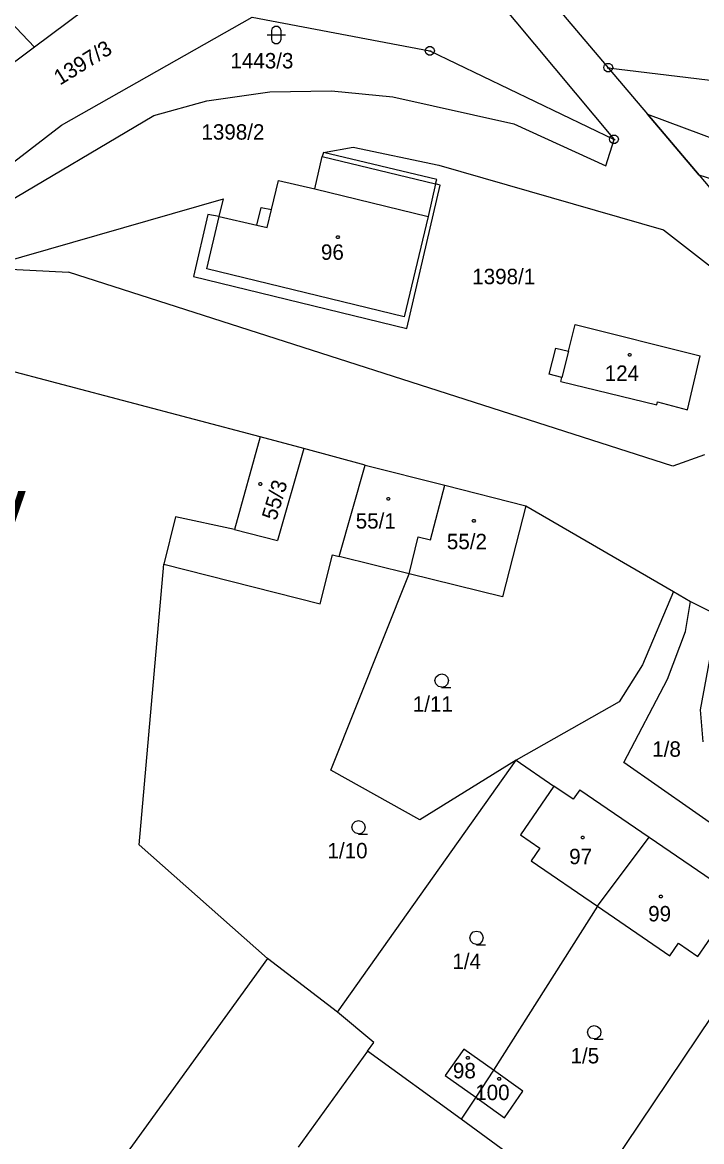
# Model space of a CAD drawing. Extents: x -850689 to -847910, y -1058374 to -1054747.
# Drawn here: x -849326.1 to -849251.2, y -1056373.6 to -1056250.1 of the extents above; entities that cross this region are included whole.
import ezdxf

# ---------------------------------------------------------------- set-up
doc = ezdxf.new("R2010")
doc.units = 0
for name, color, linetype in [('KN_BREMENA', 7, 'Continuous'), ('KN_HRANICE', 7, 'Continuous'), ('KN_KULTURY', 7, 'Continuous'), ('KN_MEZNIKY', 7, 'Continuous'), ('KN_PARCELY', 7, 'Continuous'), ('KN_SLUCKY', 7, 'Continuous'), ('KN_STAVEBNI', 7, 'Continuous')]:
    doc.layers.add(name, color=color, linetype=linetype)

# ---------------------------------------------------------------- blocks, each defined once
blk = doc.blocks.new('304')
blk.add_lwpolyline([(0, 0), (-0.38, 0.1), (-0.65, 0.37), (-0.75, 0.74), (-0.65, 1.11), (-0.38, 1.38), (-0.01, 1.48), (0.36, 1.38), (0.63, 1.11), (0.73, 0.73), (0.63, 0.35), (0.36, 0.08), (-0.02, -0.02), (0.98, -0.02)])
blk = doc.blocks.new('316')
for points in [[(-0.5, 1.5), (-0.4, 1.79), (-0.15, 1.97), (0.16, 1.97), (0.41, 1.79), (0.51, 1.5), (0.51, 0.5), (0.41, 0.21), (0.16, 0.03), (-0.15, 0.03), (-0.4, 0.21), (-0.5, 0.5), (-0.5, 1.5)], [(-1, 1), (0.27, 1), (1, 1)]]:
    blk.add_lwpolyline(points)
blk = doc.blocks.new('105')
blk.add_line((-0.12, 0), (0.12, 0))
blk.add_lwpolyline([(0.15, 0.48), (0.4, 0.3), (0.5, 0.01), (0.4, -0.28), (0.15, -0.46), (-0.16, -0.46), (-0.41, -0.28), (-0.51, 0.01), (-0.41, 0.3), (-0.16, 0.48), (0.15, 0.48)])
blk = doc.blocks.new('402')
blk.add_lwpolyline([(0.09, 0.15), (0.18, 0), (0.09, -0.15), (-0.09, -0.15), (-0.18, 0), (-0.09, 0.15), (0.09, 0.15)])

msp = doc.modelspace()

# ---------------------------------------------------------------- linework, layer by layer
at = {"layer": 'KN_BREMENA'}
msp.add_lwpolyline([(-849236.23, -1056271.84), (-849251.43, -1056266.98), (-849257.13, -1056260.24), (-849234.71, -1056268.6)], close=True, dxfattribs=at)
at = {"layer": 'KN_HRANICE'}
for p, q in [((-849279.99, -1056240.09), (-849260.83, -1056263.03)), ((-849273.62, -1056240.78), (-849261.46, -1056255.12)), ((-849335.27, -1056241.92), (-849324.78, -1056252.85)), ((-849310.77, -1056242.39), (-849324.78, -1056252.85)), ((-849321.82, -1056261.46), (-849300.76, -1056249.55)), ((-849300.76, -1056249.55), (-849281.15, -1056253.26)), ((-849324.78, -1056252.85), (-849332.91, -1056258.92)), ((-849281.15, -1056253.26), (-849260.83, -1056263.03)), ((-849261.46, -1056255.12), (-849257.13, -1056260.24)), ((-849261.46, -1056255.12), (-849225.25, -1056259.54)), ((-849305.78, -1056258.79), (-849298.81, -1056257.8)), ((-849298.81, -1056257.8), (-849292.01, -1056257.69)), ((-849292.01, -1056257.69), (-849285.23, -1056258.34)), ((-849311.64, -1056260.39), (-849305.78, -1056258.79)), ((-849285.23, -1056258.34), (-849271.88, -1056261.33)), ((-849257.13, -1056260.24), (-849251.43, -1056266.98)), ((-849341.54, -1056276.65), (-849321.82, -1056261.46)), ((-849338.74, -1056276.48), (-849311.64, -1056260.39)), ((-849271.88, -1056261.33), (-849261.72, -1056265.96)), ((-849292.89, -1056264.47), (-849289.64, -1056263.9)), ((-849289.64, -1056263.9), (-849280.17, -1056265.87)), ((-849261.72, -1056265.96), (-849260.83, -1056263.03)), ((-849293.85, -1056268.49), (-849293.05, -1056264.93)), ((-849292.89, -1056264.47), (-849293.05, -1056264.93)), ((-849280.38, -1056267.45), (-849292.89, -1056264.47)), ((-849280.17, -1056265.87), (-849255.38, -1056273.01)), ((-849298.64, -1056270.78), (-849297.86, -1056267.56)), ((-849297.86, -1056267.56), (-849293.85, -1056268.49)), ((-849280.52, -1056267.92), (-849280.38, -1056267.45)), ((-849251.43, -1056266.98), (-849249.09, -1056269.78)), ((-849283.7, -1056283.9), (-849280.01, -1056268.08)), ((-849280.01, -1056268.08), (-849280.52, -1056267.92)), ((-849330.43, -1056277.22), (-849303.93, -1056269.58)), ((-849304.4, -1056271.53), (-849303.93, -1056269.58)), ((-849305.65, -1056271.33), (-849307.26, -1056278.16)), ((-849304.4, -1056271.53), (-849305.65, -1056271.33)), ((-849300.26, -1056272.48), (-849299.77, -1056270.54)), ((-849299.77, -1056270.54), (-849298.64, -1056270.78)), ((-849304.4, -1056271.53), (-849300.26, -1056272.48)), ((-849255.38, -1056273.01), (-849249.72, -1056277.39)), ((-849330.43, -1056277.22), (-849321.06, -1056277.69)), ((-849254.33, -1056299.1), (-849321.06, -1056277.69)), ((-849307.26, -1056278.16), (-849283.7, -1056283.9)), ((-849265.86, -1056286.42), (-849265.11, -1056283.46)), ((-849265.11, -1056283.46), (-849251.31, -1056286.91)), ((-849299.89, -1056295.86), (-849343.49, -1056284.33)), ((-849267.99, -1056288.94), (-849267.27, -1056286.07)), ((-849267.27, -1056286.07), (-849265.86, -1056286.42)), ((-849252.72, -1056292.88), (-849251.31, -1056286.91)), ((-849266.58, -1056289.3), (-849267.99, -1056288.94)), ((-849266.69, -1056289.75), (-849266.58, -1056289.3)), ((-849266.69, -1056289.75), (-849256.11, -1056292.32)), ((-849256.11, -1056292.32), (-849256.03, -1056292)), ((-849256.03, -1056292), (-849252.72, -1056292.88)), ((-849299.89, -1056295.86), (-849302.72, -1056306.09)), ((-849295.08, -1056297.16), (-849299.89, -1056295.86)), ((-849288.31, -1056299), (-849295.08, -1056297.16)), ((-849250.85, -1056297.85), (-849254.33, -1056299.1)), ((-849291.17, -1056309.06), (-849288.31, -1056299)), ((-849288.31, -1056299), (-849279.52, -1056301.18)), ((-849281.07, -1056307.24), (-849279.52, -1056301.18)), ((-849279.52, -1056301.18), (-849270.57, -1056303.47)), ((-849270.57, -1056303.47), (-849273.15, -1056313.52)), ((-849270.57, -1056303.47), (-849254.26, -1056312.92)), ((-849309.23, -1056304.7), (-849310.53, -1056309.9)), ((-849302.72, -1056306.09), (-849309.23, -1056304.7)), ((-849283.45, -1056310.97), (-849282.44, -1056306.89)), ((-849282.44, -1056306.89), (-849281.07, -1056307.24)), ((-849293.26, -1056314.27), (-849291.9, -1056308.87)), ((-849291.9, -1056308.87), (-849291.17, -1056309.06)), ((-849283.45, -1056310.97), (-849291.17, -1056309.06)), ((-849313.23, -1056340.88), (-849310.53, -1056309.9)), ((-849310.53, -1056309.9), (-849293.26, -1056314.27)), ((-849292.1, -1056332.65), (-849283.45, -1056310.97)), ((-849273.15, -1056313.52), (-849283.45, -1056310.97)), ((-849254.26, -1056312.92), (-849257.7, -1056321.02)), ((-849254.26, -1056312.92), (-849252.37, -1056314.02)), ((-849252.95, -1056317.34), (-849252.37, -1056314.02)), ((-849252.37, -1056314.02), (-849249.52, -1056315.45)), ((-849254.93, -1056322.6), (-849252.95, -1056317.34)), ((-849250, -1056318.83), (-849251.32, -1056325.99)), ((-849257.7, -1056321.02), (-849260.26, -1056325.11)), ((-849259.75, -1056331.81), (-849254.93, -1056322.6)), ((-849260.26, -1056325.11), (-849271.64, -1056331.55)), ((-849251.32, -1056325.99), (-849251.01, -1056329.53)), ((-849291.34, -1056359.34), (-849271.64, -1056331.55)), ((-849271.64, -1056331.55), (-849282.25, -1056338.14)), ((-849271.64, -1056331.55), (-849267.48, -1056334.39)), ((-849244.73, -1056342.28), (-849259.75, -1056331.81)), ((-849282.25, -1056338.14), (-849292.1, -1056332.65)), ((-849267.48, -1056334.39), (-849271.16, -1056339.78)), ((-849265.33, -1056335.85), (-849267.48, -1056334.39)), ((-849264.6, -1056334.81), (-849265.33, -1056335.85)), ((-849264.6, -1056334.81), (-849256.96, -1056340.03)), ((-849271.16, -1056339.78), (-849269.01, -1056341.24)), ((-849262.65, -1056347.66), (-849256.96, -1056340.03)), ((-849256.96, -1056340.03), (-849249.3, -1056345.26)), ((-849299.09, -1056353.44), (-849313.23, -1056340.88)), ((-849269.01, -1056341.24), (-849269.98, -1056342.65)), ((-849269.98, -1056342.65), (-849262.65, -1056347.66)), ((-849262.65, -1056347.66), (-849274.12, -1056365.74)), ((-849262.65, -1056347.66), (-849254.67, -1056353.12)), ((-849251.57, -1056353.21), (-849247.87, -1056347.82)), ((-849264.25, -1056380.97), (-849243.84, -1056350.56)), ((-849254.67, -1056353.12), (-849253.72, -1056351.73)), ((-849253.72, -1056351.73), (-849251.57, -1056353.21)), ((-849299.09, -1056353.44), (-849325.93, -1056390.5)), ((-849291.34, -1056359.34), (-849299.09, -1056353.44)), ((-849287.35, -1056362.68), (-849291.34, -1056359.34)), ((-849288.04, -1056363.64), (-849287.35, -1056362.68)), ((-849288.04, -1056363.64), (-849295.68, -1056374.24)), ((-849277.71, -1056371.17), (-849288.04, -1056363.64)), ((-849277.39, -1056363.43), (-849279.45, -1056366.33)), ((-849274.12, -1056365.74), (-849277.39, -1056363.43)), ((-849279.45, -1056366.33), (-849276.09, -1056368.72)), ((-849274.12, -1056365.74), (-849276.09, -1056368.72)), ((-849270.88, -1056368.05), (-849274.12, -1056365.74)), ((-849276.09, -1056368.72), (-849277.71, -1056371.17)), ((-849276.09, -1056368.72), (-849272.9, -1056370.99)), ((-849272.9, -1056370.99), (-849270.88, -1056368.05)), ((-849264.25, -1056380.97), (-849277.71, -1056371.17))]:
    msp.add_line(p, q, dxfattribs=at)
at = {"layer": 'KN_SLUCKY'}
for p, q in [((-849293.05, -1056264.93), (-849280.52, -1056267.92)), ((-849293.85, -1056268.49), (-849281.34, -1056271.54)), ((-849280.52, -1056267.92), (-849281.34, -1056271.54)), ((-849299.11, -1056272.77), (-849298.64, -1056270.78)), ((-849305.79, -1056277.31), (-849304.4, -1056271.53)), ((-849300.26, -1056272.48), (-849299.11, -1056272.77)), ((-849281.34, -1056271.54), (-849283.98, -1056282.62)), ((-849283.98, -1056282.62), (-849305.79, -1056277.31)), ((-849265.86, -1056286.42), (-849266.58, -1056289.3)), ((-849295.08, -1056297.16), (-849297.98, -1056307.31)), ((-849302.72, -1056306.09), (-849297.98, -1056307.31))]:
    msp.add_line(p, q, dxfattribs=at)
at = {"layer": 'KN_STAVEBNI'}
for p, q in [((-849298.64, -1056270.78), (-849297.86, -1056267.56)), ((-849297.86, -1056267.56), (-849293.85, -1056268.49)), ((-849293.85, -1056268.49), (-849281.34, -1056271.54)), ((-849299.11, -1056272.77), (-849298.64, -1056270.78)), ((-849305.79, -1056277.31), (-849304.4, -1056271.53)), ((-849304.4, -1056271.53), (-849300.26, -1056272.48)), ((-849300.26, -1056272.48), (-849299.11, -1056272.77)), ((-849281.34, -1056271.54), (-849283.98, -1056282.62)), ((-849283.98, -1056282.62), (-849305.79, -1056277.31)), ((-849265.86, -1056286.42), (-849265.11, -1056283.46)), ((-849265.11, -1056283.46), (-849251.31, -1056286.91)), ((-849265.86, -1056286.42), (-849266.58, -1056289.3)), ((-849252.72, -1056292.88), (-849251.31, -1056286.91)), ((-849266.69, -1056289.75), (-849266.58, -1056289.3)), ((-849266.69, -1056289.75), (-849256.11, -1056292.32)), ((-849256.11, -1056292.32), (-849256.03, -1056292)), ((-849256.03, -1056292), (-849252.72, -1056292.88)), ((-849299.89, -1056295.86), (-849302.72, -1056306.09)), ((-849295.08, -1056297.16), (-849299.89, -1056295.86)), ((-849295.08, -1056297.16), (-849297.98, -1056307.31)), ((-849291.17, -1056309.06), (-849288.31, -1056299)), ((-849288.31, -1056299), (-849279.52, -1056301.18)), ((-849281.07, -1056307.24), (-849279.52, -1056301.18)), ((-849281.07, -1056307.24), (-849279.52, -1056301.18)), ((-849279.52, -1056301.18), (-849270.57, -1056303.47)), ((-849270.57, -1056303.47), (-849273.15, -1056313.52)), ((-849302.72, -1056306.09), (-849297.98, -1056307.31)), ((-849283.45, -1056310.97), (-849282.44, -1056306.89)), ((-849283.45, -1056310.97), (-849282.44, -1056306.89)), ((-849282.44, -1056306.89), (-849281.07, -1056307.24)), ((-849282.44, -1056306.89), (-849281.07, -1056307.24)), ((-849283.45, -1056310.97), (-849291.17, -1056309.06)), ((-849273.15, -1056313.52), (-849283.45, -1056310.97)), ((-849267.48, -1056334.39), (-849271.16, -1056339.78)), ((-849265.33, -1056335.85), (-849267.48, -1056334.39)), ((-849264.6, -1056334.81), (-849265.33, -1056335.85)), ((-849264.6, -1056334.81), (-849256.96, -1056340.03)), ((-849271.16, -1056339.78), (-849269.01, -1056341.24)), ((-849262.65, -1056347.66), (-849256.96, -1056340.03)), ((-849262.65, -1056347.66), (-849256.96, -1056340.03)), ((-849256.96, -1056340.03), (-849249.3, -1056345.26)), ((-849269.01, -1056341.24), (-849269.98, -1056342.65)), ((-849269.98, -1056342.65), (-849262.65, -1056347.66)), ((-849262.65, -1056347.66), (-849254.67, -1056353.12)), ((-849251.57, -1056353.21), (-849247.87, -1056347.82)), ((-849254.67, -1056353.12), (-849253.72, -1056351.73)), ((-849253.72, -1056351.73), (-849251.57, -1056353.21)), ((-849299.09, -1056353.44), (-849325.93, -1056390.5)), ((-849291.34, -1056359.34), (-849299.09, -1056353.44)), ((-849287.35, -1056362.68), (-849291.34, -1056359.34)), ((-849288.04, -1056363.64), (-849287.35, -1056362.68)), ((-849288.04, -1056363.64), (-849295.68, -1056374.24)), ((-849277.39, -1056363.43), (-849279.45, -1056366.33)), ((-849274.12, -1056365.74), (-849277.39, -1056363.43)), ((-849279.45, -1056366.33), (-849276.09, -1056368.72)), ((-849274.12, -1056365.74), (-849276.09, -1056368.72)), ((-849274.12, -1056365.74), (-849276.09, -1056368.72)), ((-849270.88, -1056368.05), (-849274.12, -1056365.74)), ((-849276.09, -1056368.72), (-849272.9, -1056370.99)), ((-849272.9, -1056370.99), (-849270.88, -1056368.05))]:
    msp.add_line(p, q, dxfattribs=at)

# ---------------------------------------------------------------- block references
at = {"layer": 'KN_KULTURY'}
for name, p in [('316', (-849298.11, -1056252.5)), ('402', (-849291.32, -1056273.83)), ('402', (-849259.1, -1056286.8)), ('402', (-849299.87, -1056301.06)), ('402', (-849285.74, -1056302.7)), ('402', (-849276.31, -1056305.12)), ('304', (-849279.84, -1056323.49)), ('304', (-849289.02, -1056339.67)), ('402', (-849264.29, -1056340.08)), ('402', (-849255.65, -1056346.59)), ('304', (-849276, -1056351.88)), ('304', (-849263, -1056362.3)), ('402', (-849276.97, -1056364.39)), ('402', (-849273.52, -1056366.71))]:
    msp.add_blockref(name, p, dxfattribs=at)
at = {"layer": 'KN_MEZNIKY'}
for p in [(-849281.15, -1056253.26), (-849261.46, -1056255.12), (-849260.83, -1056263.03)]:
    msp.add_blockref('105', p, dxfattribs=at)

# ---------------------------------------------------------------- texts
at = {"layer": 'KN_PARCELY'}
for s, rotation, p in [('1397/3', 31.742, (-849321.99, -1056257.11)), ('55/3', 73.339, (-849298.12, -1056305.17))]:
    msp.add_text(s, height=1.7, rotation=rotation, dxfattribs=at).set_placement(p)
for s, height, p in [('1443/3', 1.7, (-849303.17, -1056255.2)), ('1398/2', 1.7, (-849306.37, -1056263.06)), ('96', 1.7, (-849293.18, -1056276.32)), ('1398/1', 1.7, (-849276.48, -1056279.01)), ('124', 1.7, (-849261.86, -1056289.68)), ('Cebiv', 6.7, (-849348.64, -1056306.99)), ('55/1', 1.7, (-849289.34, -1056305.98)), ('55/2', 1.7, (-849279.28, -1056308.26)), ('1/11', 1.7, (-849283.04, -1056326.19)), ('1/8', 1.7, (-849256.61, -1056331.16)), ('1/10', 1.7, (-849292.46, -1056342.37)), ('97', 1.7, (-849265.78, -1056343.02)), ('99', 1.7, (-849257.06, -1056349.33)), ('1/4', 1.7, (-849278.67, -1056354.58)), ('1/5', 1.7, (-849265.63, -1056365)), ('98', 1.7, (-849278.61, -1056366.65)), ('100', 1.7, (-849276.15, -1056369.05))]:
    msp.add_text(s, height=height, dxfattribs=at).set_placement(p)

doc.saveas('drawing.dxf')
